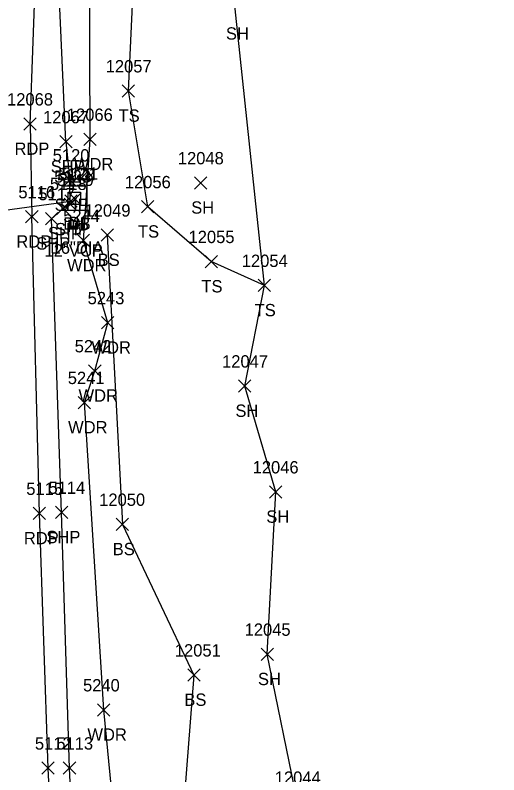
# Model space of a CAD drawing. Extents: x 1769141 to 1770911, y 735471 to 741449.
# Drawn here: x 1770770 to 1770848.4, y 739482.3 to 739605.5 of the extents above; entities that cross this region are included whole.
import ezdxf

# ---------------------------------------------------------------- set-up
doc = ezdxf.new("R2010")
doc.units = 0
for name, color, linetype in [('D_A', 7, 'Continuous'), ('D_C', 7, 'Continuous'), ('D_I', 7, 'Continuous'), ('D_TIC', 7, 'Continuous'), ('DCP', 7, 'Continuous'), ('DS', 7, 'Continuous'), ('L_A', 7, 'Continuous'), ('L_I', 7, 'Continuous'), ('L_TIC', 7, 'Continuous'), ('LAWA', 7, 'Continuous'), ('LELB', 7, 'Continuous'), ('LSOGP', 7, 'Continuous'), ('P_A', 7, 'Continuous'), ('P_I', 7, 'Continuous'), ('P_TIC', 7, 'Continuous'), ('PET', 7, 'Continuous'), ('PSP', 7, 'Continuous')]:
    doc.layers.add(name, color=color, linetype=linetype)

msp = doc.modelspace()

# ---------------------------------------------------------------- linework, layer by layer
at = {"layer": 'D_TIC'}
for points in [[(1770778.06, 739574.34), (1770780.06, 739576.34)], [(1770780.06, 739574.34), (1770778.06, 739576.34)], [(1770778.71, 739574.7), (1770780.71, 739576.7)], [(1770780.71, 739574.7), (1770778.71, 739576.7)]]:
    msp.add_lwpolyline(points, dxfattribs=at)
at = {"layer": 'DCP'}
msp.add_lwpolyline([(1770731.92, 739568.92), (1770779.06, 739575.34)], dxfattribs=at)
at = {"layer": 'DS'}
for p, q in [((1770777.64, 739577.79), (1770781.64, 739577.79)), ((1770777.64, 739573.79), (1770777.64, 739577.79)), ((1770781.64, 739577.79), (1770781.64, 739573.79)), ((1770778.64, 739574.79), (1770778.64, 739576.79)), ((1770778.64, 739576.79), (1770780.64, 739576.79)), ((1770780.64, 739576.79), (1770780.64, 739574.79)), ((1770780.64, 739574.79), (1770778.64, 739574.79)), ((1770779.65, 739575.8), (1770779.65, 739575.8)), ((1770779.65, 739575.8), (1770779.65, 739575.8)), ((1770781.64, 739573.79), (1770777.64, 739573.79))]:
    msp.add_line(p, q, dxfattribs=at)
at = {"layer": 'L_TIC'}
for points in [[(1770787.37, 739592.2), (1770789.37, 739594.2)], [(1770789.37, 739592.2), (1770787.37, 739594.2)], [(1770781.18, 739584.35), (1770783.18, 739586.35)], [(1770783.18, 739584.35), (1770781.18, 739586.35)], [(1770799.06, 739577.3), (1770801.06, 739579.3)], [(1770801.06, 739577.3), (1770799.06, 739579.3)], [(1770790.52, 739573.42), (1770792.52, 739575.42)], [(1770792.52, 739573.42), (1770790.52, 739575.42)], [(1770780.08, 739567.95), (1770782.08, 739569.95)], [(1770782.08, 739567.95), (1770780.08, 739569.95)], [(1770783.96, 739568.82), (1770785.96, 739570.82)], [(1770785.96, 739568.82), (1770783.96, 739570.82)], [(1770800.79, 739564.53), (1770802.79, 739566.53)], [(1770802.79, 739564.53), (1770800.79, 739566.53)], [(1770809.41, 739560.66), (1770811.41, 739562.66)], [(1770811.41, 739560.66), (1770809.41, 739562.66)], [(1770784.04, 739554.61), (1770786.04, 739556.61)], [(1770786.04, 739554.61), (1770784.04, 739556.61)], [(1770781.94, 739546.81), (1770783.94, 739548.81)], [(1770783.94, 739546.81), (1770781.94, 739548.81)], [(1770806.22, 739544.35), (1770808.22, 739546.35)], [(1770808.22, 739544.35), (1770806.22, 739546.35)], [(1770780.25, 739541.67), (1770782.25, 739543.67)], [(1770782.25, 739541.67), (1770780.25, 739543.67)], [(1770811.23, 739527.18), (1770813.23, 739529.18)], [(1770813.23, 739527.18), (1770811.23, 739529.18)], [(1770786.4, 739521.92), (1770788.4, 739523.92)], [(1770788.4, 739521.92), (1770786.4, 739523.92)], [(1770809.87, 739500.85), (1770811.87, 739502.85)], [(1770811.87, 739500.85), (1770809.87, 739502.85)], [(1770798, 739497.49), (1770800, 739499.49)], [(1770800, 739497.49), (1770798, 739499.49)], [(1770783.38, 739491.83), (1770785.38, 739493.83)], [(1770785.38, 739491.83), (1770783.38, 739493.83)]]:
    msp.add_lwpolyline(points, dxfattribs=at)
at = {"layer": 'LAWA'}
for points in [[(1770782.18, 739585.35), (1770782.01, 739628.12), (1770780.93, 739666.42), (1770784.06, 739682.06), (1770783.66, 739692.74), (1770786.37, 739709.83), (1770787.02, 739747.9)], [(1770781.08, 739568.95), (1770782.18, 739585.35)], [(1770848.36, 739299.29), (1770819.39, 739316.36), (1770796.34, 739325.69), (1770784.74, 739317.06), (1770772.09, 739329.99), (1770772.76, 739337.11), (1770771.58, 739344.84), (1770780.05, 739365.89), (1770784.26, 739398.35), (1770789.18, 739434.08), (1770793.15, 739450.42), (1770787.55, 739460.71), (1770784.38, 739492.83), (1770781.25, 739542.67), (1770782.94, 739547.81), (1770785.04, 739555.61), (1770781.08, 739568.95)]]:
    msp.add_lwpolyline(points, dxfattribs=at)
at = {"layer": 'LELB'}
for points in [[(1770810.41, 739561.66), (1770801.79, 739565.53), (1770791.52, 739574.42), (1770788.37, 739593.2), (1770789.47, 739616.51), (1770794.6, 739637.96), (1770791.13, 739656.98), (1770807.16, 739660.65)], [(1770784.96, 739569.82), (1770787.4, 739522.92), (1770799, 739498.49), (1770797.19, 739475.62), (1770796.74, 739459.69)]]:
    msp.add_lwpolyline(points, dxfattribs=at)
at = {"layer": 'LSOGP'}
msp.add_lwpolyline([(1770815.75, 739477.85), (1770810.87, 739501.85), (1770812.23, 739528.18), (1770807.22, 739545.35), (1770810.41, 739561.66), (1770805.68, 739606.52), (1770809.5, 739636.8), (1770807.16, 739660.65), (1770804.31, 739691.06), (1770799.56, 739701.22), (1770787.02, 739747.9), (1770782.69, 739750.16), (1770779.35, 739750.36), (1770770.93, 739751.13), (1770759.37, 739752.68), (1770758.49, 739752.81), (1770755.58, 739753.04), (1770751.61, 739753.67), (1770744.11, 739754.07), (1770722.16, 739768.68), (1770712.51, 739778.18)], dxfattribs=at)
at = {"layer": 'P_TIC'}
for points in [[(1770771.45, 739586.84), (1770773.45, 739588.84)], [(1770773.45, 739586.84), (1770771.45, 739588.84)], [(1770777.26, 739583.95), (1770779.26, 739585.95)], [(1770779.26, 739583.95), (1770777.26, 739585.95)], [(1770777.9, 739577.76), (1770779.9, 739579.76)], [(1770779.9, 739577.76), (1770777.9, 739579.76)], [(1770776.8, 739573.14), (1770778.8, 739575.14)], [(1770778.8, 739573.14), (1770776.8, 739575.14)], [(1770777.96, 739573.79), (1770779.96, 739575.79)], [(1770779.96, 739573.79), (1770777.96, 739575.79)], [(1770771.74, 739571.79), (1770773.74, 739573.79)], [(1770773.74, 739571.79), (1770771.74, 739573.79)], [(1770774.93, 739571.48), (1770776.93, 739573.48)], [(1770776.93, 739571.48), (1770774.93, 739573.48)], [(1770772.97, 739523.69), (1770774.97, 739525.69)], [(1770774.97, 739523.69), (1770772.97, 739525.69)], [(1770776.57, 739523.87), (1770778.57, 739525.87)], [(1770778.57, 739523.87), (1770776.57, 739525.87)], [(1770774.37, 739482.39), (1770776.37, 739484.39)], [(1770776.37, 739482.39), (1770774.37, 739484.39)], [(1770777.84, 739482.4), (1770779.84, 739484.4)], [(1770779.84, 739482.4), (1770777.84, 739484.4)]]:
    msp.add_lwpolyline(points, dxfattribs=at)
at = {"layer": 'PET'}
for points in [[(1770772.45, 739587.84), (1770773.9, 739628.1), (1770773.75, 739666.51), (1770775.87, 739710.61), (1770779.35, 739750.36)], [(1770772.45, 739587.84), (1770772.74, 739572.79)], [(1770826.12, 739215.62), (1770808.71, 739238.73), (1770793.69, 739255.36), (1770777.1, 739279.15), (1770747.52, 739317.6), (1770746.21, 739323.83), (1770749.6, 739332.28), (1770764.58, 739363.7), (1770773.77, 739402.23), (1770777.46, 739441.59), (1770775.37, 739483.39), (1770773.97, 739524.69), (1770772.74, 739572.79)]]:
    msp.add_lwpolyline(points, dxfattribs=at)
at = {"layer": 'PSP'}
for points in [[(1770778.26, 739584.95), (1770776.31, 739628.33), (1770777.52, 739666.41), (1770779.03, 739710.51), (1770782.69, 739750.16)], [(1770778.26, 739584.95), (1770778.9, 739578.76)], [(1770777.1, 739279.15), (1770772.36, 739289.78), (1770763.28, 739301.07), (1770753.08, 739312.06), (1770750.64, 739316.97), (1770751.24, 739320.46), (1770749.65, 739321.47), (1770748.44, 739321.99), (1770752.14, 739330.24), (1770753.96, 739331.67), (1770766.54, 739361.54), (1770776.63, 739402.31), (1770780.9, 739440.8), (1770778.84, 739483.4), (1770777.57, 739524.87), (1770775.93, 739572.48), (1770777.8, 739574.14), (1770778.96, 739574.79), (1770778.9, 739578.76)]]:
    msp.add_lwpolyline(points, dxfattribs=at)

# ---------------------------------------------------------------- texts
at = {"layer": 'D_A'}
for s, p in [('DIB', (1770777.81, 739570.7)), ('P', (1770778.44, 739570.34)), ('DI', (1770778.7, 739570.8))]:
    msp.add_text(s, height=2, dxfattribs=at).set_placement(p)
at = {"layer": 'D_C'}
for s, p in [('16"DIA', (1770775.95, 739566.8)), ('12"VCP', (1770774.8, 739566.34))]:
    msp.add_text(s, height=2, dxfattribs=at).set_placement(p)
at = {"layer": 'D_I'}
for s, p in [('5123', (1770776.37, 739578.34)), ('5122', (1770777.02, 739578.7)), ('5121', (1770777.52, 739578.8))]:
    msp.add_text(s, height=2, dxfattribs=at).set_placement(p)
at = {"layer": 'L_A'}
for s, p in [('SH', (1770804.17, 739601.52)), ('TS', (1770786.78, 739588.2)), ('WDR', (1770779.55, 739580.35)), ('SH', (1770798.55, 739573.3)), ('TS', (1770789.93, 739569.42)), ('BS', (1770783.4, 739564.82)), ('WDR', (1770778.44, 739563.95)), ('TS', (1770800.2, 739560.53)), ('TS', (1770808.82, 739556.66)), ('WDR', (1770782.4, 739550.61)), ('WDR', (1770780.3, 739542.81)), ('SH', (1770805.71, 739540.35)), ('WDR', (1770778.61, 739537.67)), ('SH', (1770810.71, 739523.18)), ('BS', (1770785.84, 739517.92)), ('SH', (1770809.36, 739496.85)), ('BS', (1770797.44, 739493.49)), ('WDR', (1770781.74, 739487.83))]:
    msp.add_text(s, height=2, dxfattribs=at).set_placement(p)
at = {"layer": 'L_I'}
for s, p in [('12057', (1770784.7, 739596.2)), ('12066', (1770778.41, 739588.35)), ('12048', (1770796.39, 739581.3)), ('12056', (1770787.8, 739577.42)), ('12049', (1770781.28, 739572.82)), ('5244', (1770777.82, 739571.95)), ('12055', (1770798.12, 739568.53)), ('12054', (1770806.74, 739564.66)), ('5243', (1770781.78, 739558.61)), ('5242', (1770779.68, 739550.81)), ('12047', (1770803.55, 739548.35)), ('5241', (1770778.56, 739545.67)), ('12046', (1770808.5, 739531.18)), ('12050', (1770783.65, 739525.92)), ('12045', (1770807.2, 739504.85)), ('12051', (1770795.9, 739501.49)), ('5240', (1770781.03, 739495.83)), ('12044', (1770812.08, 739480.85))]:
    msp.add_text(s, height=2, dxfattribs=at).set_placement(p)
at = {"layer": 'P_A'}
for s, p in [('RDP', (1770769.93, 739582.84)), ('SHP', (1770775.8, 739579.95)), ('SHP', (1770776.44, 739573.76)), ('SHP', (1770775.34, 739569.14)), ('SHP', (1770776.49, 739569.79)), ('RDP', (1770770.23, 739567.79)), ('SHP', (1770773.46, 739567.48)), ('SHP', (1770775.1, 739519.87)), ('RDP', (1770771.45, 739519.69))]:
    msp.add_text(s, height=2, dxfattribs=at).set_placement(p)
at = {"layer": 'P_I'}
for s, p in [('12068', (1770768.73, 739590.84)), ('12067', (1770774.55, 739587.95)), ('5120', (1770776.12, 739581.76)), ('5119', (1770776.82, 739577.79)), ('5118', (1770775.67, 739577.14)), ('5116', (1770770.56, 739575.79)), ('5117', (1770773.8, 739575.48)), ('5115', (1770771.84, 739527.69)), ('5114', (1770775.44, 739527.87)), ('5112', (1770773.24, 739486.39)), ('5113', (1770776.71, 739486.4))]:
    msp.add_text(s, height=2, dxfattribs=at).set_placement(p)

doc.saveas('drawing.dxf')
